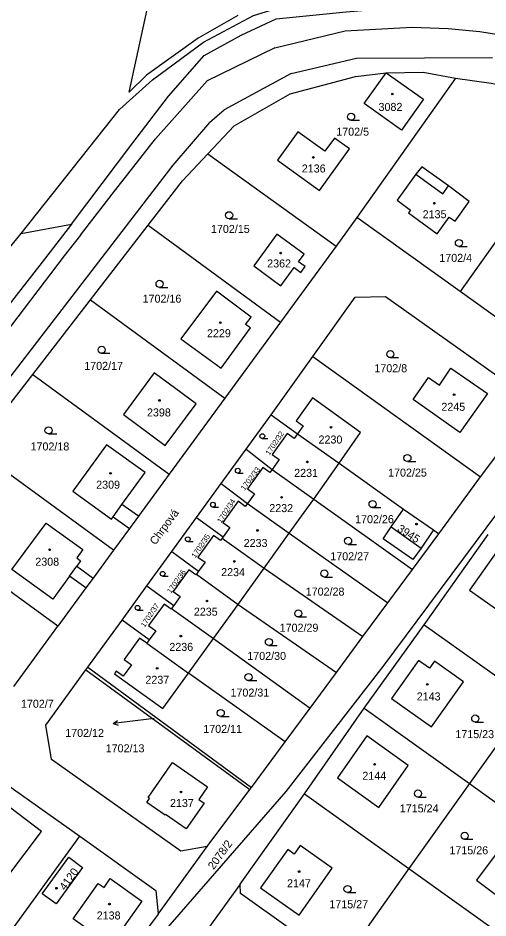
# Model space of a CAD drawing. Extents: x -679220 to -673243, y -1075091 to -1066557.
# Drawn here: x -677019.6 to -676919.9, y -1071935.7 to -1071744.6 of the extents above; entities that cross this region are included whole.
import ezdxf

# ---------------------------------------------------------------- set-up
doc = ezdxf.new("R2010")
doc.units = 0
for name, color, linetype in [('Hranice parcel', 7, 'Continuous'), ('Parcelní čísla', 7, 'Continuous'), ('Pop  PČ popisy', 7, 'Continuous'), ('Vnitřní kresba', 7, 'Continuous'), ('Značky budov', 7, 'Continuous'), ('Značky kultur', 7, 'Continuous')]:
    doc.layers.add(name, color=color, linetype=linetype)

msp = doc.modelspace()

# ---------------------------------------------------------------- linework, layer by layer
at = {"layer": 'Hranice parcel'}
for p, q in [((-676926.82, -1071757.39), (-676947.75, -1071786.97)), ((-676979.38, -1071773.47), (-676952.12, -1071793.06)), ((-676910.26, -1071780.74), (-676925.83, -1071802.72)), ((-677018.95, -1071790.41), (-677008.25, -1071788.41)), ((-677004.27, -1071804.47), (-676992.04, -1071788.64)), ((-676992.04, -1071788.64), (-676963.93, -1071809.2)), ((-676947.75, -1071786.97), (-676952.12, -1071793.06)), ((-676925.83, -1071802.72), (-676947.75, -1071786.97)), ((-677022.61, -1071794.93), (-677018.95, -1071790.41)), ((-676952.12, -1071793.06), (-676963.93, -1071809.2)), ((-677016.51, -1071820.3), (-677004.27, -1071804.47)), ((-677004.27, -1071804.47), (-676975.73, -1071825.35)), ((-676963.93, -1071809.2), (-676975.73, -1071825.35)), ((-676965.92, -1071828.88), (-676957.07, -1071816.5)), ((-676957.07, -1071816.5), (-676921.47, -1071842.02)), ((-677028.76, -1071836.15), (-677016.51, -1071820.3)), ((-677016.51, -1071820.3), (-676987.54, -1071841.49)), ((-676975.73, -1071825.35), (-676987.54, -1071841.49)), ((-676971.22, -1071836.15), (-676965.92, -1071828.88)), ((-676965.92, -1071828.88), (-676960.33, -1071832.91)), ((-676921.47, -1071842.02), (-676912.06, -1071829.42)), ((-676960.33, -1071832.91), (-676951.51, -1071839.18)), ((-676999.37, -1071857.63), (-677028.76, -1071836.15)), ((-676976.5, -1071843.44), (-676971.22, -1071836.15)), ((-676971.22, -1071836.15), (-676965.73, -1071840.47)), ((-676956.88, -1071846.78), (-676951.51, -1071839.18)), ((-676951.51, -1071839.18), (-676937.83, -1071848.89)), ((-676987.54, -1071841.49), (-676994.09, -1071850.42)), ((-676965.73, -1071840.47), (-676956.88, -1071846.78)), ((-676930.31, -1071854.12), (-676921.47, -1071842.02)), ((-676981.75, -1071850.71), (-676976.5, -1071843.44)), ((-676976.5, -1071843.44), (-676970.96, -1071847.68)), ((-676970.96, -1071847.68), (-676962.06, -1071853.99)), ((-676962.06, -1071853.99), (-676956.88, -1071846.78)), ((-676956.88, -1071846.78), (-676935.9, -1071861.71)), ((-676937.83, -1071848.89), (-676931.44, -1071853.33)), ((-676994.09, -1071850.42), (-676995.99, -1071853.02)), ((-676986.97, -1071857.92), (-676981.75, -1071850.71)), ((-676981.75, -1071850.71), (-676976.1, -1071854.77)), ((-677011.17, -1071873.78), (-677040.99, -1071851.99)), ((-676995.99, -1071853.02), (-676999.37, -1071857.63)), ((-676931.44, -1071853.33), (-676930.31, -1071854.12)), ((-676976.1, -1071854.77), (-676976.33, -1071855.1)), ((-676976.33, -1071855.1), (-676967.43, -1071861.45)), ((-676967.43, -1071861.45), (-676962.06, -1071853.99)), ((-676962.06, -1071853.99), (-676941.16, -1071868.83)), ((-676935.9, -1071861.71), (-676930.31, -1071854.12)), ((-676933.43, -1071873.45), (-676919.84, -1071854.28)), ((-676999.37, -1071857.63), (-677003.69, -1071863.54)), ((-676992.26, -1071865.22), (-676986.97, -1071857.92)), ((-676986.97, -1071857.92), (-676981.3, -1071862.06)), ((-676981.3, -1071862.06), (-676981.78, -1071862.72)), ((-676981.78, -1071862.72), (-676972.95, -1071869.15)), ((-676972.95, -1071869.15), (-676967.43, -1071861.45)), ((-676967.43, -1071861.45), (-676946.44, -1071875.98)), ((-676941.16, -1071868.83), (-676935.9, -1071861.71)), ((-677003.69, -1071863.54), (-677005.22, -1071865.64)), ((-677005.22, -1071865.64), (-677011.17, -1071873.78)), ((-676997.52, -1071872.51), (-676992.26, -1071865.22)), ((-676992.26, -1071865.22), (-676986.6, -1071869.37)), ((-676946.44, -1071875.98), (-676941.16, -1071868.83)), ((-676986.6, -1071869.37), (-676987.04, -1071869.98)), ((-676987.04, -1071869.98), (-676978.18, -1071876.36)), ((-676978.18, -1071876.36), (-676972.95, -1071869.15)), ((-676972.95, -1071869.15), (-676952.05, -1071883.58)), ((-677004.84, -1071882.45), (-676997.52, -1071872.51)), ((-676991.77, -1071876.65), (-676997.52, -1071872.51)), ((-677020.49, -1071886.53), (-677011.17, -1071873.78)), ((-676946.15, -1071891.15), (-676933.43, -1071873.45)), ((-676933.43, -1071873.45), (-676916.35, -1071885.64)), ((-676983.45, -1071883.71), (-676978.18, -1071876.36)), ((-676978.18, -1071876.36), (-676957.63, -1071891.14)), ((-676952.05, -1071883.58), (-676946.44, -1071875.98)), ((-676991.77, -1071876.65), (-676992.28, -1071877.37)), ((-676992.28, -1071877.37), (-676983.45, -1071883.71)), ((-677005.23, -1071883), (-677004.84, -1071882.45)), ((-677005.23, -1071883), (-676970.45, -1071908.43)), ((-677004.84, -1071882.45), (-676970.1, -1071908.03)), ((-676962.91, -1071898.29), (-676983.45, -1071883.71)), ((-676957.63, -1071891.14), (-676952.05, -1071883.58)), ((-676911.17, -1071889.33), (-676923.86, -1071907.18)), ((-676962.91, -1071898.29), (-676957.63, -1071891.14)), ((-676958.87, -1071909.35), (-676946.15, -1071891.15)), ((-676946.15, -1071891.15), (-676923.86, -1071907.18)), ((-676970.1, -1071908.03), (-676962.91, -1071898.29)), ((-677025.4, -1071904.97), (-677006.52, -1071918.32)), ((-676923.86, -1071907.18), (-676936.67, -1071925.2)), ((-676923.86, -1071907.18), (-676901.29, -1071923.42)), ((-676979.52, -1071920.52), (-676970.45, -1071908.43)), ((-676970.45, -1071908.43), (-676970.1, -1071908.03)), ((-676972.46, -1071928.53), (-676958.87, -1071909.35)), ((-676958.87, -1071909.35), (-676936.67, -1071925.2)), ((-677027, -1071946.58), (-677006.52, -1071918.32)), ((-676989.9, -1071934.91), (-676979.52, -1071920.52)), ((-676936.67, -1071925.2), (-676951.19, -1071945.63)), ((-676936.67, -1071925.2), (-676914.04, -1071941.35)), ((-676972.46, -1071928.53), (-676980.07, -1071938.97)), ((-676989.9, -1071934.91), (-677007.25, -1071958.24))]:
    msp.add_line(p, q, dxfattribs=at)
for points in [[(-676972.99, -1071744.11), (-676981.37, -1071748.94), (-676992.4, -1071756.81), (-676996.06, -1071760.38), (-676985.11, -1071709.91)], [(-677018.95, -1071790.41), (-676998.13, -1071764.06), (-676991.09, -1071757.75), (-676980.3, -1071749.81), (-676969.65, -1071744.11), (-676948.02, -1071737.42), (-676927.88, -1071735.23), (-676874.21, -1071743.78), (-676842.93, -1071743.5), (-676823.69, -1071740.46)], [(-677008.25, -1071788.41), (-676995.25, -1071771.16), (-676987.7, -1071761.27), (-676980.12, -1071752.62), (-676972.27, -1071748.26), (-676964.86, -1071744.84), (-676950.01, -1071743.35), (-676935.78, -1071742.14), (-676921.36, -1071742.37), (-676911.47, -1071742.59), (-676889.65, -1071747.32), (-676853.71, -1071753.48), (-676844.92, -1071752.82), (-676823.69, -1071740.46)], [(-676979.38, -1071773.47), (-676973.79, -1071767.51), (-676961.91, -1071760.71), (-676948.02, -1071757.07), (-676941.48, -1071756.28), (-676933.68, -1071756.17), (-676926.82, -1071757.39)], [(-676933.57, -1071761.89), (-676938.27, -1071768.43), (-676946.18, -1071762.82), (-676941.48, -1071756.28), (-676933.57, -1071761.89)], [(-676926.82, -1071757.39), (-676919.25, -1071758.51), (-676905.07, -1071761.28)], [(-676955.69, -1071781.23), (-676949.32, -1071772.45), (-676952.5, -1071770.14), (-676954.53, -1071772.93), (-676960.23, -1071768.8), (-676964.55, -1071774.8), (-676955.69, -1071781.23)], [(-676992.04, -1071788.64), (-676984.76, -1071779.21), (-676979.38, -1071773.47)], [(-676928.28, -1071780.28), (-676933.96, -1071776.21), (-676935.22, -1071777.81), (-676939.18, -1071783.32), (-676936.34, -1071785.45), (-676936.75, -1071786.01)], [(-676936.75, -1071786.01), (-676930.66, -1071790.43), (-676928.15, -1071786.9), (-676926.89, -1071787.8), (-676923.88, -1071783.58), (-676928.28, -1071780.28)], [(-677008.25, -1071788.41), (-677013.98, -1071795.82), (-677072.5, -1071870.78), (-677089.07, -1071891.97), (-677097.96, -1071902.91), (-677118.79, -1071928.36)], [(-676958.92, -1071794.79), (-676964.71, -1071790.56), (-676969.62, -1071797.27), (-676963.83, -1071801.51), (-676961, -1071797.64), (-676959.61, -1071798.65), (-676958.73, -1071797.43), (-676960.11, -1071796.42), (-676958.92, -1071794.79)], [(-676970.3, -1071810.43), (-676971.33, -1071809.68), (-676970.16, -1071808.18), (-676977.51, -1071802.64), (-676985.07, -1071812.72), (-676976.54, -1071818.96), (-676970.3, -1071810.43)], [(-676957.07, -1071816.5), (-676948.08, -1071803.91), (-676941.64, -1071803.78), (-676915.86, -1071822.06), (-676912.06, -1071829.42)], [(-676902.63, -1071816.93), (-676905.53, -1071817.31), (-676925.83, -1071802.72)], [(-676927.82, -1071818.97), (-676920.04, -1071824.39), (-676925.87, -1071832.66), (-676935.8, -1071825.6), (-676932.51, -1071820.94), (-676930.18, -1071822.59), (-676927.82, -1071818.97)], [(-676997.27, -1071828.85), (-676988.39, -1071835.4), (-676981.84, -1071826.52), (-676990.72, -1071819.97), (-676997.27, -1071828.85)], [(-676951.51, -1071839.18), (-676946.93, -1071832.63), (-676957.11, -1071825.28), (-676960.62, -1071830.16), (-676959.13, -1071831.23), (-676960.33, -1071832.91)], [(-677004.82, -1071960.24), (-676990.19, -1071940.38), (-676962.75, -1071908.83), (-676942.14, -1071882.34), (-676915.32, -1071846.3), (-676903, -1071827.69)], [(-676960.33, -1071832.91), (-676961.05, -1071833.92), (-676962.52, -1071832.87), (-676965.73, -1071837.34), (-676964.24, -1071838.4), (-676965.73, -1071840.47)], [(-676994.09, -1071850.42), (-676997.57, -1071847.92), (-676992.67, -1071841.13), (-677000.88, -1071835.29), (-677007.98, -1071845.12), (-676999.82, -1071851.02), (-676999.44, -1071850.53), (-676995.99, -1071853.02)], [(-676965.73, -1071840.47), (-676966.22, -1071841.15), (-676967.71, -1071840.08), (-676970.94, -1071844.59), (-676969.48, -1071845.63), (-676970.96, -1071847.68)], [(-676970.96, -1071847.68), (-676971.42, -1071848.33), (-676972.92, -1071847.25), (-676976.14, -1071851.72), (-676974.67, -1071852.78), (-676976.1, -1071854.77)], [(-676931.44, -1071853.33), (-676934.07, -1071857.17), (-676935.88, -1071859.58), (-676942.13, -1071855.18), (-676940.48, -1071852.69), (-676937.83, -1071848.89)], [(-677005.22, -1071865.64), (-677008.7, -1071863.14), (-677012.24, -1071868.03), (-677020.96, -1071861.72), (-677013.66, -1071851.9), (-677005.88, -1071857.48), (-677007.18, -1071859.28), (-677006.34, -1071859.87), (-677007.17, -1071861.02), (-677003.69, -1071863.54)], [(-676976.33, -1071855.1), (-676976.66, -1071855.55), (-676978.14, -1071854.49), (-676981.45, -1071859.11), (-676979.95, -1071860.19), (-676981.3, -1071862.06)], [(-676909.94, -1071863.66), (-676918.02, -1071857.93), (-676923.8, -1071866.09), (-676915.72, -1071871.82), (-676909.94, -1071863.66)], [(-676981.78, -1071862.72), (-676981.89, -1071862.88), (-676983.41, -1071861.79), (-676986.71, -1071866.4), (-676985.23, -1071867.46), (-676986.6, -1071869.37)], [(-676987.04, -1071869.98), (-676987.16, -1071870.15), (-676988.65, -1071869.08), (-676991.92, -1071873.63), (-676990.39, -1071874.73), (-676991.77, -1071876.65)], [(-676992.28, -1071877.37), (-676993.82, -1071876.27), (-676997.1, -1071880.85), (-676995.57, -1071881.95), (-676997.33, -1071884.4), (-676998.8, -1071883.34), (-676999.18, -1071883.87), (-676988.93, -1071891.22), (-676983.45, -1071883.71)], [(-676931.87, -1071895.14), (-676925.07, -1071885.55), (-676931.24, -1071881.17), (-676932.3, -1071882.69), (-676934.63, -1071881.04), (-676940.36, -1071889.12), (-676931.87, -1071895.14)], [(-676979.52, -1071920.52), (-676985.05, -1071921.52), (-677012.52, -1071902.05), (-677013.74, -1071894.76), (-677005.23, -1071883)], [(-676943.05, -1071912.25), (-676936.82, -1071903.31), (-676945.61, -1071897.04), (-676951.85, -1071905.98), (-676943.05, -1071912.25)], [(-676992.27, -1071911.16), (-676991.7, -1071910.31), (-676992.01, -1071910.1), (-676986.84, -1071902.68), (-676979.42, -1071907.85), (-676981.29, -1071910.53), (-676980.15, -1071911.32), (-676983.95, -1071916.77), (-676988.32, -1071913.73), (-676988.4, -1071913.84), (-676992.27, -1071911.16)], [(-677014.64, -1071917.37), (-677024.73, -1071909.71), (-677032.1, -1071919.42), (-677022.01, -1071927.08), (-677014.64, -1071917.37)], [(-677006.52, -1071918.32), (-676990.41, -1071929.86), (-676989.9, -1071934.91)], [(-676959.96, -1071935.1), (-676952.94, -1071925.16), (-676959.78, -1071920.33), (-676961.05, -1071922.12), (-676962.38, -1071921.14), (-676968.17, -1071929.3), (-676959.96, -1071935.1)], [(-676909.23, -1071925.12), (-676916.5, -1071919.81), (-676922.35, -1071927.67), (-676914.7, -1071933.38), (-676909.23, -1071925.12)], [(-677005.94, -1071924.98), (-677011.53, -1071932.72), (-677014.48, -1071930.59), (-677008.86, -1071922.81), (-677005.94, -1071924.98)], [(-677000.04, -1071941.54), (-677007.96, -1071935.89), (-677002.6, -1071928.37), (-677001.38, -1071929.24), (-677000.07, -1071927.33), (-676993.33, -1071932.13), (-677000.04, -1071941.54)], [(-676951.19, -1071945.63), (-676972.45, -1071930.47), (-676972.46, -1071928.53)]]:
    msp.add_lwpolyline(points, dxfattribs=at)
at = {"layer": 'Pop  PČ popisy'}
for p, q in [((-676999.42, -1071894.42), (-676998.49, -1071893.8)), ((-676990.76, -1071893.35), (-676996.44, -1071894.05)), ((-676996.44, -1071894.05), (-676999.42, -1071894.42)), ((-676999.42, -1071894.42), (-676998.36, -1071894.79))]:
    msp.add_line(p, q, dxfattribs=at)
at = {"layer": 'Vnitřní kresba'}
for p, q in [((-676950.2, -1071747.36), (-676935.99, -1071746.58)), ((-676935.99, -1071746.58), (-676928.36, -1071746.84)), ((-676965.15, -1071750.96), (-676950.2, -1071747.36)), ((-676928.36, -1071746.84), (-676921.61, -1071747.51)), ((-676921.61, -1071747.51), (-676911.77, -1071749.08)), ((-676965.15, -1071750.96), (-676979.48, -1071758.01)), ((-676961.7, -1071756.42), (-676947.84, -1071753.18)), ((-676947.84, -1071753.18), (-676918.92, -1071753.04)), ((-676979.48, -1071758.01), (-676990.47, -1071770.3)), ((-676961.7, -1071756.42), (-676975.87, -1071764.14)), ((-676979.03, -1071766.86), (-676977.37, -1071765.39)), ((-676977.37, -1071765.39), (-676975.87, -1071764.14)), ((-676979.03, -1071766.86), (-676986.75, -1071775.9)), ((-676999.65, -1071782.04), (-676990.47, -1071770.3)), ((-676986.75, -1071775.9), (-677036.69, -1071840.72)), ((-676935.22, -1071777.81), (-676929.52, -1071781.96)), ((-676929.52, -1071781.96), (-676928.28, -1071780.28)), ((-677006.4, -1071790.78), (-676999.65, -1071782.04)), ((-677006.4, -1071790.78), (-677009.81, -1071795.15)), ((-677009.81, -1071795.15), (-677113.2, -1071930.1)), ((-676999.44, -1071850.53), (-676997.57, -1071847.92)), ((-676940.48, -1071852.69), (-676934.07, -1071857.17)), ((-677008.7, -1071863.14), (-677007.17, -1071861.02))]:
    msp.add_line(p, q, dxfattribs=at)
at = {"layer": 'Značky budov'}
for centre in [(-676940.22, -1071760.79), (-676956.95, -1071774.25), (-676931.29, -1071783.97), (-676963.88, -1071794.56), (-676976.7, -1071809.31), (-676927.09, -1071824.6), (-676989.61, -1071825.84), (-676953.21, -1071831.51), (-676958.23, -1071838.88), (-677000, -1071841.31), (-676963.69, -1071846.41), (-676968.8, -1071853.43), (-676935.07, -1071852.09), (-677012.93, -1071857.54), (-676973.73, -1071860.01), (-676979.53, -1071868.41), (-676985.07, -1071875.86), (-676990.09, -1071882.71), (-676932.79, -1071886.11), (-676943.96, -1071903.1), (-676985.06, -1071908.94), (-676959.98, -1071925.85), (-677011.46, -1071929.38), (-677000.22, -1071932.76)]:
    msp.add_circle(centre, 0.175, dxfattribs=at)
at = {"layer": 'Značky kultur'}
for p, q in [((-676948.95, -1071766.36), (-676947.2, -1071766.36)), ((-676974.83, -1071787.27), (-676973.08, -1071787.27)), ((-676926.08, -1071793.15), (-676924.33, -1071793.15)), ((-676989.59, -1071801.83), (-676987.84, -1071801.83)), ((-677001.88, -1071815.83), (-677000.13, -1071815.83)), ((-676940.63, -1071816.75), (-676938.88, -1071816.75)), ((-677013.16, -1071832.94), (-677011.41, -1071832.94)), ((-676967.79, -1071833.91), (-676966.61, -1071833.91)), ((-676937, -1071838.81), (-676935.25, -1071838.81)), ((-676972.99, -1071841.24), (-676971.82, -1071841.24)), ((-676978.28, -1071848.46), (-676977.1, -1071848.46)), ((-676944.4, -1071848.59), (-676942.65, -1071848.59)), ((-676983.6, -1071855.79), (-676982.43, -1071855.79)), ((-676949.59, -1071856.39), (-676947.84, -1071856.39)), ((-676988.94, -1071863.12), (-676987.76, -1071863.12)), ((-676954.62, -1071863.32), (-676952.87, -1071863.32)), ((-676994.27, -1071870.34), (-676993.09, -1071870.34)), ((-676960.16, -1071871.8), (-676958.41, -1071871.8)), ((-676966.39, -1071877.87), (-676964.64, -1071877.87)), ((-676970.72, -1071885.32), (-676968.97, -1071885.32)), ((-676976.61, -1071892.94), (-676974.86, -1071892.94)), ((-676922.62, -1071894.11), (-676920.87, -1071894.11)), ((-676934.76, -1071910.02), (-676933.01, -1071910.02)), ((-676924.86, -1071919), (-676923.11, -1071919)), ((-676949.71, -1071930.3), (-676947.96, -1071930.3))]:
    msp.add_line(p, q, dxfattribs=at)
for centre, radius in [((-676948.95, -1071765.61), 0.75), ((-676974.83, -1071786.52), 0.75), ((-676926.08, -1071792.4), 0.75), ((-676989.59, -1071801.08), 0.75), ((-677001.88, -1071815.08), 0.75), ((-676940.63, -1071816), 0.75), ((-677013.16, -1071832.19), 0.75), ((-676967.79, -1071833.41), 0.502), ((-676937, -1071838.06), 0.75), ((-676973, -1071840.74), 0.502), ((-676978.28, -1071847.96), 0.502), ((-676944.4, -1071847.84), 0.75), ((-676983.61, -1071855.29), 0.502), ((-676949.59, -1071855.64), 0.75), ((-676988.94, -1071862.62), 0.502), ((-676954.62, -1071862.57), 0.75), ((-676994.27, -1071869.84), 0.502), ((-676960.16, -1071871.05), 0.75), ((-676966.39, -1071877.12), 0.75), ((-676970.72, -1071884.57), 0.75), ((-676976.61, -1071892.19), 0.75), ((-676922.62, -1071893.36), 0.75), ((-676934.76, -1071909.27), 0.75), ((-676924.86, -1071918.25), 0.75), ((-676949.71, -1071929.55), 0.75)]:
    msp.add_circle(centre, radius, dxfattribs=at)

# ---------------------------------------------------------------- texts
at = {"layer": 'Parcelní čísla'}
for s, p in [('3082', (-676943.13, -1071764.37)), ('1702/5', (-676952.1, -1071769.63)), ('2136', (-676959.42, -1071777.44)), ('2135', (-676933.77, -1071787.15)), ('1702/15', (-676978.68, -1071790.27)), ('2362', (-676966.76, -1071797.6)), ('1702/4', (-676930.23, -1071796.41)), ('1702/16', (-676993.19, -1071805.08)), ('2229', (-676979.53, -1071812.41)), ('1702/17', (-677005.57, -1071819.34)), ('1702/8', (-676944.01, -1071819.84)), ('2245', (-676929.8, -1071828.03)), ('2398', (-676992.26, -1071829.23)), ('2230', (-676955.86, -1071834.98)), ('1702/18', (-677016.97, -1071836.45)), ('2231', (-676961.03, -1071842.06)), ('1702/25', (-676941.1, -1071842)), ('2309', (-677003.04, -1071844.57)), ('2232', (-676966.31, -1071849.54)), ('1702/26', (-676948.1, -1071851.89)), ('2233', (-676971.75, -1071856.95)), ('2308', (-677015.96, -1071860.92)), ('1702/27', (-676953.36, -1071859.76)), ('2234', (-676976.53, -1071863.13)), ('1702/28', (-676958.58, -1071867.26)), ('2235', (-676982.32, -1071871.53)), ('1702/29', (-676964.11, -1071874.93)), ('2236', (-676987.52, -1071879)), ('1702/30', (-676970.98, -1071880.92)), ('2237', (-676992.6, -1071885.98)), ('1702/31', (-676974.54, -1071888.7)), ('2143', (-676935.03, -1071889.52)), ('1702/7', (-677019, -1071891.07)), ('1702/12', (-677009.61, -1071897.26)), ('1702/11', (-676980.31, -1071896.41)), ('1715/23', (-676926.83, -1071897.52)), ('1702/13', (-677001.02, -1071900.53)), ('2144', (-676946.56, -1071906.36)), ('2137', (-676987.38, -1071912.14)), ('1715/24', (-676938.62, -1071913.28)), ('1715/26', (-676928.09, -1071922.18)), ('2147', (-676962.54, -1071929.18)), ('1715/27', (-676953.56, -1071933.63)), ('2138', (-677002.93, -1071936.02))]:
    msp.add_text(s, height=1.7, dxfattribs=at).set_placement(p)
for s, height, rotation, p in [('1702/32', 1.14, 56, (-676966.29, -1071837.58)), ('1702/33', 1.14, 53, (-676971.57, -1071845.05)), ('1702/34', 1.14, 57, (-676976.52, -1071851.99)), ('3945', 1.7, 327, (-676939.3, -1071853.46)), ('1702/35', 1.14, 56, (-676981.99, -1071859.39)), ('1702/36', 1.14, 55, (-676987.2, -1071866.91)), ('1702/37', 1.14, 56, (-676992.77, -1071874.11)), ('2078/2', 1.7, 54, (-676978.12, -1071925.57)), ('4120', 1.7, 54, (-677009.64, -1071929.97))]:
    msp.add_text(s, height=height, rotation=rotation, dxfattribs=at).set_placement(p)
at = {"layer": 'Pop  PČ popisy'}
msp.add_text('Chrpová', height=1.7, rotation=54, dxfattribs=at).set_placement((-676990.46, -1071856.64))

doc.saveas('drawing.dxf')
